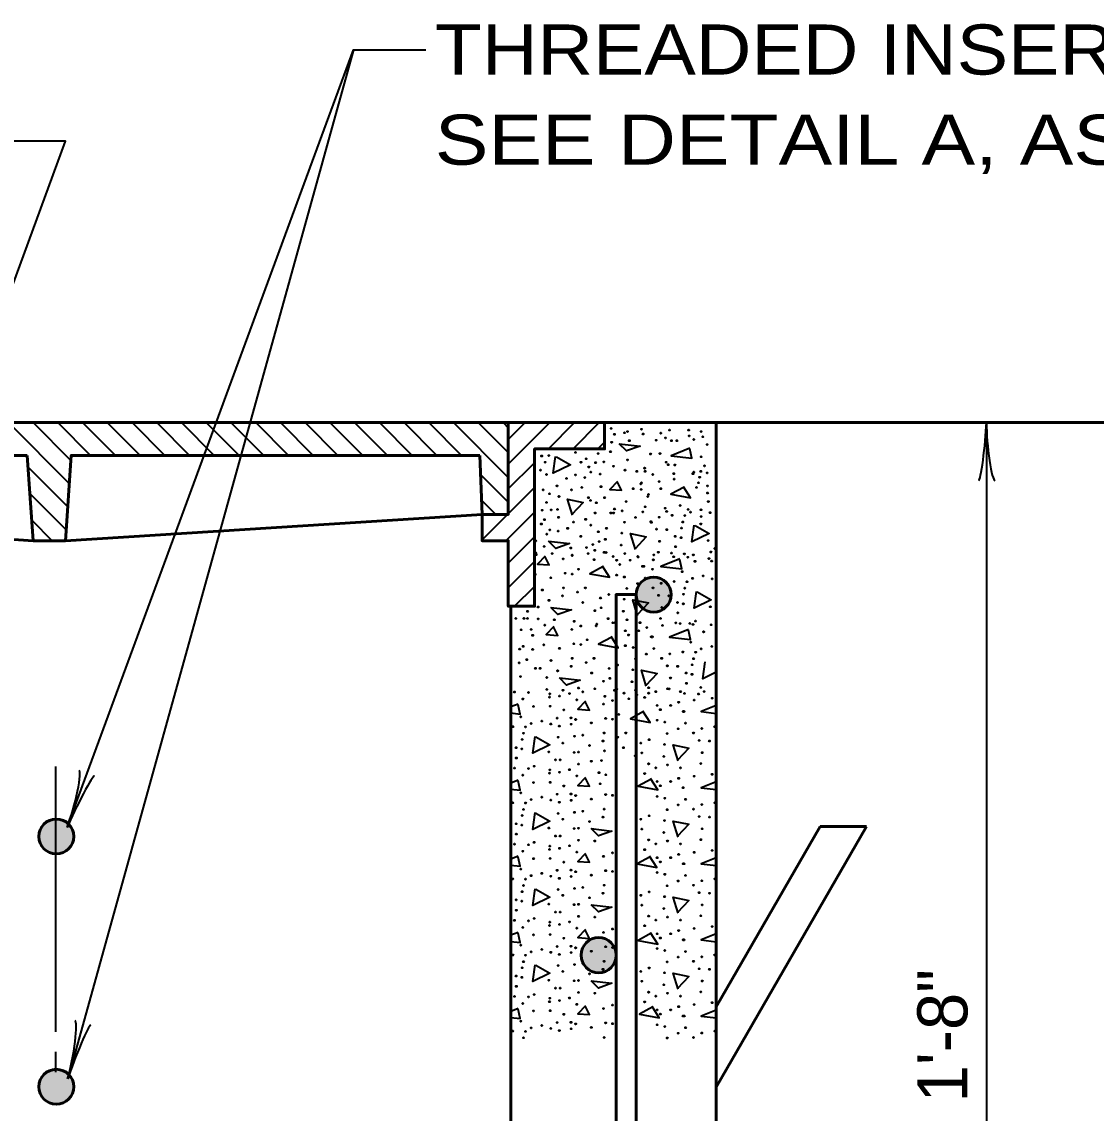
# Model space of a CAD drawing. Extents: x 788 to 1469, y -1 to 439.
# Drawn here: x 915.7 to 969.3, y 161.4 to 215.9 of the extents above; entities that cross this region are included whole.
import ezdxf

# ---------------------------------------------------------------- set-up
doc = ezdxf.new("R2010")
doc.units = 0
doc.layers.add('1', color=7, linetype='Continuous', lineweight=35)

msp = doc.modelspace()

# ---------------------------------------------------------------- hatches: boundary and pattern name
at = {"layer": '1'}
for points in [[(946.356, 187.287, 1), (948.101, 187.287, 1)], [(918.275, 175.212, 1), (916.531, 175.212, 1)], [(943.607, 169.287, 1), (945.361, 169.287, 1)], [(918.275, 162.716, 1), (916.531, 162.716, 1)]]:
    msp.add_hatch(color=256, dxfattribs=at).paths.add_polyline_path(points)

# ---------------------------------------------------------------- linework, layer by layer
for p, q in [((932.243, 214.486), (935.856, 214.486)), ((915.011, 195.872), (918.052, 192.831)), ((916.245, 195.872), (918.131, 193.986)), ((917.481, 195.872), (919.118, 194.235)), ((918.716, 195.872), (920.353, 194.235)), ((919.95, 195.872), (921.588, 194.235)), ((921.185, 195.872), (922.823, 194.235)), ((922.42, 195.872), (924.058, 194.235)), ((923.655, 195.872), (925.293, 194.235)), ((924.89, 195.872), (926.528, 194.235)), ((926.125, 195.872), (927.763, 194.235)), ((927.36, 195.872), (928.998, 194.235)), ((928.595, 195.872), (930.233, 194.235)), ((929.83, 195.872), (931.468, 194.235)), ((931.065, 195.872), (932.703, 194.235)), ((932.3, 195.872), (933.938, 194.235)), ((933.535, 195.872), (935.173, 194.235)), ((934.77, 195.872), (936.408, 194.235)), ((936.005, 195.872), (937.643, 194.235)), ((937.24, 195.872), (939.973, 193.14)), ((938.475, 195.872), (939.973, 194.375)), ((939.71, 195.872), (939.973, 195.609)), ((939.973, 195.033), (940.812, 195.872)), ((939.973, 193.798), (942.047, 195.872)), ((941.972, 194.562), (943.281, 195.872)), ((943.207, 194.562), (944.516, 195.872)), ((944.442, 194.562), (944.776, 194.897)), ((915.99, 193.657), (917.972, 191.675)), ((939.973, 192.564), (941.283, 193.873)), ((938.586, 193.291), (939.973, 191.904)), ((916.082, 192.331), (917.892, 190.52)), ((939.973, 191.328), (941.283, 192.638)), ((938.635, 192.007), (939.355, 191.287)), ((938.663, 190.019), (939.932, 191.287)), ((939.857, 189.978), (941.283, 191.403)), ((916.173, 191.004), (917.2, 189.978)), ((939.973, 188.859), (941.283, 190.168)), ((939.973, 187.624), (941.283, 188.933)), ((940.287, 186.703), (941.283, 187.698)), ((940.469, 181.824), (940.106, 181.677)), ((917.356, 178.703), (917.356, 165.453)), ((940.469, 178.024), (940.106, 177.877)), ((940.469, 174.224), (940.106, 174.077)), ((940.469, 170.424), (940.106, 170.277)), ((940.469, 166.624), (940.106, 166.477)), ((917.356, 164.453), (917.356, 163.453))]:
    msp.add_line(p, q, dxfattribs=at)
at = {"layer": '1', "lineweight": 53}
for p, q in [((894.126, 195.872), (939.973, 195.872)), ((939.973, 195.872), (950.356, 195.872)), ((939.973, 195.872), (939.973, 192.597)), ((950.356, 195.872), (950.356, 165.102)), ((950.356, 195.872), (999.683, 195.872)), ((915.95, 194.235), (895.549, 194.235)), ((938.55, 194.235), (938.663, 191.287)), ((895.436, 191.287), (916.244, 189.978)), ((917.855, 189.978), (938.663, 191.287)), ((940.106, 165.102), (940.106, 186.703)), ((950.356, 162.703), (957.856, 175.703)), ((950.356, 166.705), (955.547, 175.703)), ((957.856, 175.703), (955.547, 175.703)), ((940.106, 132.643), (940.106, 165.102)), ((950.356, 132.643), (950.356, 165.102))]:
    msp.add_line(p, q, dxfattribs=at)
at = {"layer": '1'}
for points in [[(917.95, 175.662), (932.243, 214.486), (917.979, 163.119)], [(911.684, 193.114), (917.856, 209.928), (913.665, 209.928)], [(963.856, 195.872), (963.856, 142.203), (963.856, 131.723), (963.856, 121.729), (963.856, 90.479)], [(949.04, 194.6), (948.1, 194.22), (949.14, 194.1), (949.04, 194.56)], [(942.373, 194.169), (943.073, 193.769), (942.213, 193.349), (942.333, 194.189)], [(945.42, 192.94), (945.04, 192.54), (945.62, 192.5), (945.42, 192.9)], [(948.751, 192.656), (948.091, 192.296), (949.072, 192.116), (948.712, 192.676)], [(943.173, 191.25), (942.933, 192.05), (943.712, 191.89), (943.152, 191.29)], [(949.3, 190.734), (950, 190.334), (949.14, 189.914), (949.26, 190.754)], [(946.32, 189.534), (946.08, 190.334), (946.861, 190.174), (946.3, 189.574)], [(941.809, 189.21), (941.429, 188.81), (942.009, 188.77), (941.809, 189.17)], [(948.529, 189.07), (947.589, 188.69), (948.629, 188.57), (948.529, 189.03)], [(944.709, 188.69), (944.049, 188.33), (945.029, 188.15), (944.669, 188.71)], [(949.409, 187.43), (950.109, 187.03), (949.249, 186.61), (949.369, 187.45)], [(946.429, 186.23), (946.189, 187.03), (946.969, 186.87), (946.409, 186.27)], [(942.242, 185.69), (941.862, 185.29), (942.442, 185.25), (942.242, 185.65)], [(948.962, 185.55), (948.022, 185.17), (949.062, 185.05), (948.962, 185.51)], [(945.142, 185.17), (944.482, 184.81), (945.462, 184.63), (945.102, 185.19)], [(950.356, 183.42), (949.682, 183.09), (949.802, 183.93)], [(946.862, 182.71), (946.622, 183.51), (947.402, 183.35), (946.842, 182.75)], [(940.106, 181.377), (940.569, 181.324), (940.469, 181.784)], [(943.829, 181.964), (943.449, 181.564), (944.029, 181.524), (943.829, 181.924)], [(946.729, 181.444), (946.069, 181.084), (947.049, 180.904), (946.689, 181.464)], [(950.356, 181.746), (949.609, 181.444), (950.356, 181.358)], [(941.349, 180.184), (942.049, 179.784), (941.189, 179.364), (941.309, 180.204)], [(948.449, 178.984), (948.209, 179.784), (948.989, 179.624), (948.429, 179.024)], [(940.106, 177.577), (940.569, 177.524), (940.469, 177.984)], [(943.829, 178.164), (943.449, 177.764), (944.029, 177.724), (943.829, 178.124)], [(947.114, 178.08), (946.454, 177.72), (947.434, 177.54), (947.074, 178.1)], [(950.356, 177.946), (949.609, 177.644), (950.356, 177.558)], [(941.349, 176.384), (942.049, 175.984), (941.189, 175.564), (941.309, 176.404)], [(948.449, 175.184), (948.209, 175.984), (948.989, 175.824), (948.429, 175.224)], [(943.829, 174.364), (943.449, 173.964), (944.029, 173.924), (943.829, 174.324)], [(940.106, 173.777), (940.569, 173.724), (940.469, 174.184)], [(947.062, 174.203), (946.402, 173.843), (947.382, 173.663), (947.022, 174.223)], [(950.356, 174.146), (949.609, 173.844), (950.356, 173.758)], [(941.349, 172.584), (942.049, 172.184), (941.189, 171.764), (941.309, 172.604)], [(948.449, 171.384), (948.209, 172.184), (948.989, 172.024), (948.429, 171.424)], [(943.829, 170.564), (943.449, 170.164), (944.029, 170.124), (943.829, 170.524)], [(940.106, 169.977), (940.569, 169.924), (940.469, 170.384)], [(947.114, 170.377), (946.454, 170.017), (947.434, 169.837), (947.074, 170.397)], [(950.356, 170.346), (949.609, 170.044), (950.356, 169.958)], [(941.349, 168.784), (942.049, 168.384), (941.189, 167.964), (941.309, 168.804)], [(948.449, 167.584), (948.209, 168.384), (948.989, 168.224), (948.429, 167.624)], [(943.829, 166.764), (943.449, 166.364), (944.029, 166.324), (943.829, 166.724)], [(947.191, 166.706), (946.531, 166.346), (947.511, 166.166), (947.151, 166.726)], [(940.106, 166.177), (940.569, 166.124), (940.469, 166.584)], [(950.356, 166.546), (949.609, 166.244), (950.356, 166.158)]]:
    msp.add_lwpolyline(points, dxfattribs=at)
at = {"layer": '1', "lineweight": 53}
for points in [[(944.776, 195.872), (944.776, 194.562), (941.283, 194.562), (941.283, 186.703), (939.973, 186.703), (939.973, 189.978), (938.663, 189.978), (938.663, 191.287), (939.973, 191.287), (939.973, 195.872)], [(938.55, 194.235), (918.149, 194.235), (917.855, 189.978), (916.244, 189.978), (915.95, 194.235)]]:
    msp.add_lwpolyline(points, dxfattribs=at)
at = {"layer": '1'}
for points in [[(945.513, 194.822), (946.553, 194.702), (945.873, 194.462)], [(941.981, 189.954), (943.02, 189.834), (942.341, 189.594)], [(942.089, 186.65), (943.129, 186.53), (942.449, 186.29)], [(942.522, 183.13), (943.562, 183.01), (942.882, 182.77)], [(944.109, 175.604), (945.149, 175.484), (944.469, 175.244)], [(944.109, 171.804), (945.149, 171.684), (944.469, 171.444)], [(944.109, 168.004), (945.149, 167.884), (944.469, 167.644)]]:
    msp.add_lwpolyline(points, close=True, dxfattribs=at)
at = {"layer": '1', "lineweight": 53}
msp.add_lwpolyline([(946.356, 126.703), (946.356, 187.287), (945.356, 187.287), (945.356, 127.703), (925.356, 127.703), (925.356, 126.703)], close=True, dxfattribs=at)
at = {"layer": '1'}
for centre in [(945.113, 195.582), (945.27, 195.287), (945.78, 195.366), (945.918, 195.425), (946.624, 195.543), (946.703, 195.307), (947.586, 195.346), (947.821, 195.111), (948.017, 195.503), (948.979, 195.503), (948.999, 195.209), (949.234, 195.032), (949.607, 195.425), (949.686, 195.17), (945.133, 194.895), (946.016, 194.973), (947.35, 194.993), (948.116, 194.973), (948.39, 194.973), (949.901, 194.777), (941.639, 194.208), (941.993, 194.227), (943.327, 194.384), (943.857, 194.07), (944.465, 194.326), (945.074, 194.424), (945.918, 194.011), (947.075, 194.306), (947.546, 194.326), (949.607, 194.169), (941.58, 193.501), (941.816, 193.894), (943.602, 193.894), (943.994, 193.658), (944.092, 193.403), (944.328, 193.874), (944.74, 193.913), (945.231, 193.697), (945.8, 193.501), (946.389, 193.442), (946.781, 193.599), (946.801, 193.442), (947.86, 193.894), (947.959, 193.776), (948.292, 193.756), (949.234, 193.403), (949.587, 193.442), (949.764, 193.717), (941.875, 193.285), (942.876, 193.089), (943.327, 193.265), (943.798, 193.128), (944.563, 193.305), (946.624, 192.873), (947.193, 193.285), (947.507, 192.932), (948.233, 193.324), (948.253, 193.05), (949.195, 193.324), (949.47, 192.873), (949.529, 193.148), (949.901, 193.364), (941.718, 192.519), (942.032, 192.323), (942.405, 192.716), (943.131, 192.519), (943.641, 192.637), (944.603, 192.677), (946.212, 192.578), (946.585, 192.814), (946.604, 192.539), (947.586, 192.578), (949.372, 192.637), (949.921, 192.716), (949.921, 192.362), (941.875, 191.891), (942.503, 192.186), (943.975, 192.127), (944.073, 191.989), (944.367, 191.872), (944.779, 192.127), (945.859, 191.931), (946.938, 192.186), (946.977, 192.284), (949.96, 191.931), (941.659, 191.499), (942.11, 191.518), (942.424, 191.538), (944.308, 191.361), (945.093, 191.361), (945.231, 191.361), (945.275, 191.563), (945.659, 191.471), (946.693, 191.418), (946.801, 191.675), (947.802, 191.597), (947.88, 191.44), (948.151, 191.245), (948.549, 191.736), (948.787, 191.232), (948.959, 191.538), (949.065, 191.404), (949.596, 191.524), (950.046, 191.378), (941.62, 190.812), (941.777, 191.028), (942.483, 191.145), (943.229, 190.91), (943.837, 191.047), (944.092, 190.753), (945.779, 190.901), (946.322, 191.139), (947.091, 190.927), (947.115, 190.89), (947.502, 191.152), (948.681, 190.914), (949.587, 190.812), (949.607, 191.185), (941.896, 190.304), (942.051, 190.517), (942.464, 190.458), (942.935, 190.596), (943.592, 190.198), (944.467, 190.423), (944.877, 190.596), (945.646, 190.357), (947.369, 190.556), (947.886, 190.529), (948.31, 190.198), (948.602, 190.132), (948.615, 190.609), (941.352, 189.973), (941.757, 189.693), (943.092, 189.614), (943.877, 189.634), (944.188, 189.787), (944.506, 189.933), (944.819, 190.046), (945.606, 189.76), (947.528, 189.946), (948.323, 189.681), (949.953, 189.986), (950.285, 189.588), (941.352, 189.376), (941.368, 189.281), (942.161, 189.336), (942.706, 189.069), (943.155, 189.257), (943.157, 189.241), (943.965, 189.334), (944.289, 189.496), (944.76, 189.4), (944.851, 189.389), (945.209, 189.19), (945.792, 189.336), (946.441, 189.19), (946.457, 189.162), (947.239, 189.268), (947.462, 189.402), (948.127, 189.36), (948.231, 189.177), (948.763, 189.321), (948.933, 189.151), (949.211, 189.27), (949.993, 189.084), (950.088, 189.413), (943.475, 188.552), (944.255, 189.031), (945.383, 189.002), (945.542, 188.79), (946.059, 189.002), (946.682, 188.698), (946.735, 188.698), (947.174, 188.554), (947.213, 189.025), (949.293, 188.949), (950.128, 188.963), (941.315, 188.3), (942.097, 188.127), (942.812, 188.353), (943.157, 188.313), (945.383, 188.26), (945.768, 188.167), (946.801, 188.114), (948.657, 188.432), (949.174, 188.101), (949.704, 188.22), (950.155, 188.074), (941.672, 187.518), (942.733, 187.624), (943.422, 187.412), (943.819, 187.624), (945.887, 187.597), (946.43, 187.836), (947.199, 187.624), (947.61, 187.849), (948.259, 187.942), (948.789, 187.61), (948.895, 187.929), (942.004, 187.001), (942.68, 187.226), (943.7, 186.894), (944.575, 187.12), (944.986, 187.292), (945.754, 187.054), (947.477, 187.252), (947.994, 187.226), (948.418, 186.894), (948.723, 187.305), (940.933, 186.453), (941.46, 186.669), (944.297, 186.484), (944.615, 186.629), (945.715, 186.457), (947.636, 186.643), (948.432, 186.377), (948.71, 186.828), (950.062, 186.682), (940.344, 186.1), (940.756, 186.1), (940.933, 186.1), (941.46, 186.073), (942.269, 186.033), (943.263, 185.953), (944.398, 185.814), (944.959, 186.086), (945.194, 185.88), (945.317, 185.887), (945.9, 186.033), (946.55, 185.887), (947.57, 186.099), (948.339, 185.874), (948.56, 185.84), (949.041, 185.847), (949.196, 185.801), (949.32, 185.966), (950.102, 185.781), (940.619, 185.531), (941.109, 185.55), (941.188, 185.256), (941.801, 185.761), (943.139, 185.549), (943.59, 185.721), (944.363, 185.728), (945.816, 185.482), (945.976, 185.27), (946.492, 185.482), (946.89, 185.642), (947.672, 185.748), (949.726, 185.429), (940.717, 184.706), (941.748, 184.78), (943.245, 184.833), (943.59, 184.793), (943.908, 185.032), (945.817, 184.74), (947.115, 185.178), (947.168, 185.178), (949.09, 184.912), (950.137, 184.7), (940.54, 184.569), (941.188, 184.549), (942.53, 184.607), (946.201, 184.647), (946.864, 184.316), (947.235, 184.594), (948.043, 184.329), (948.692, 184.422), (949.329, 184.409), (949.607, 184.581), (940.521, 183.882), (940.894, 184.039), (941.325, 183.607), (941.561, 183.607), (942.106, 183.998), (943.113, 183.706), (943.166, 184.104), (943.855, 183.892), (944.253, 184.104), (945.008, 183.6), (945.419, 183.772), (946.32, 184.077), (947.632, 184.104), (947.911, 183.732), (948.427, 183.706), (949.156, 183.785), (949.223, 184.09), (940.58, 183.195), (941.894, 183.149), (942.437, 183.481), (944.133, 183.374), (945.048, 183.109), (946.188, 183.534), (948.07, 183.123), (948.851, 183.374), (949.143, 183.308), (941.894, 182.553), (942.702, 182.513), (943.481, 182.626), (944.289, 182.586), (944.73, 182.964), (945.283, 182.507), (945.392, 182.566), (946.148, 182.937), (946.333, 182.513), (946.98, 182.639), (947.92, 182.586), (948.003, 182.579), (948.865, 182.857), (949.59, 182.653), (940.279, 182.427), (940.703, 182.074), (940.982, 182.401), (942.028, 182.167), (942.042, 182.334), (942.532, 182.22), (943.022, 182.348), (943.388, 182.034), (943.696, 182.433), (944.796, 182.208), (945.177, 181.995), (945.75, 182.367), (945.986, 182.087), (946.383, 182.281), (946.781, 182.154), (946.983, 182.367), (947.337, 182.44), (948.57, 182.44), (948.772, 182.354), (949.259, 182.021), (949.474, 182.327), (949.753, 182.446), (950.147, 182.114), (941.233, 181.703), (942.068, 181.716), (942.744, 181.531), (944.726, 181.822), (947.404, 181.756), (947.563, 181.544), (948.08, 181.756), (948.477, 181.915), (948.702, 181.451), (948.755, 181.451), (940.597, 181.186), (941.644, 180.974), (942.413, 181.12), (943.102, 181.133), (943.335, 181.053), (944.117, 180.881), (944.832, 181.106), (945.177, 181.067), (945.495, 181.305), (947.404, 181.014), (947.788, 180.921), (948.822, 180.868), (940.2, 180.695), (940.73, 180.364), (940.836, 180.682), (941.114, 180.854), (942.095, 180.828), (942.519, 180.722), (943.115, 180.815), (944.753, 180.377), (945.84, 180.377), (947.907, 180.351), (948.451, 180.589), (949.219, 180.377), (949.63, 180.603), (950.28, 180.695), (940.663, 180.059), (942.466, 180.165), (942.691, 179.873), (943.274, 180.218), (943.693, 180.271), (944.7, 179.979), (945.442, 180.165), (946.595, 179.873), (947.006, 180.046), (947.775, 179.807), (949.498, 180.006), (950.014, 179.979), (940.359, 179.648), (940.65, 179.582), (942.002, 179.436), (943.255, 179.407), (943.481, 179.423), (944.024, 179.754), (944.777, 179.488), (945.72, 179.648), (946.317, 179.237), (946.635, 179.383), (949.657, 179.396), (940.372, 179.131), (941.26, 178.72), (942.333, 179.038), (942.559, 179.038), (943.481, 178.826), (944.117, 178.966), (944.626, 179.001), (946.98, 178.839), (947.735, 179.211), (947.92, 178.786), (949.59, 178.853), (940.279, 178.627), (940.703, 178.274), (940.982, 178.601), (942.028, 178.367), (942.042, 178.534), (942.532, 178.42), (943.022, 178.548), (943.388, 178.234), (944.499, 178.399), (944.846, 178.295), (946.781, 178.354), (947.337, 178.64), (948.57, 178.64), (949.259, 178.221), (950.147, 178.314), (941.233, 177.903), (942.068, 177.916), (942.744, 177.731), (944.557, 177.843), (947.404, 177.956), (947.563, 177.744), (948.08, 177.956), (948.477, 178.115), (948.702, 177.651), (940.597, 177.386), (941.114, 177.054), (941.644, 177.174), (942.413, 177.32), (943.102, 177.333), (943.335, 177.253), (944.117, 177.081), (944.832, 177.306), (945.177, 177.267), (947.404, 177.214), (947.788, 177.121), (948.822, 177.068), (940.2, 176.895), (940.73, 176.564), (940.836, 176.882), (942.095, 177.028), (942.519, 176.922), (943.115, 177.015), (944.753, 176.577), (947.907, 176.551), (948.451, 176.789), (949.219, 176.577), (949.63, 176.803), (950.28, 176.895), (940.663, 176.259), (942.466, 176.365), (942.691, 176.073), (943.274, 176.418), (943.693, 176.471), (944.7, 176.179), (946.595, 176.073), (947.006, 176.246), (947.775, 176.007), (949.498, 176.206), (950.014, 176.179), (940.359, 175.848), (940.65, 175.782), (942.002, 175.636), (943.255, 175.607), (943.481, 175.623), (944.024, 175.954), (946.635, 175.583), (949.657, 175.596), (940.372, 175.331), (941.26, 174.92), (942.333, 175.238), (942.559, 175.238), (943.481, 175.026), (944.289, 174.986), (946.98, 175.039), (947.735, 175.411), (947.92, 174.986), (949.59, 175.053), (940.279, 174.827), (940.703, 174.474), (940.982, 174.801), (942.028, 174.567), (942.042, 174.734), (942.532, 174.62), (943.022, 174.748), (943.388, 174.434), (945.177, 174.395), (946.781, 174.554), (947.337, 174.84), (948.57, 174.84), (949.259, 174.421), (950.147, 174.514), (941.233, 174.103), (942.068, 174.116), (942.744, 173.931), (944.726, 174.222), (947.404, 174.156), (947.563, 173.944), (948.08, 174.156), (948.477, 174.315), (948.702, 173.851), (948.755, 173.851), (940.597, 173.586), (941.114, 173.254), (941.644, 173.374), (942.413, 173.52), (943.102, 173.533), (943.335, 173.453), (944.117, 173.281), (944.832, 173.506), (945.177, 173.467), (947.404, 173.414), (947.788, 173.321), (948.822, 173.268), (940.2, 173.095), (940.73, 172.764), (940.836, 173.082), (942.095, 173.228), (942.519, 173.122), (943.115, 173.215), (944.753, 172.777), (947.907, 172.751), (948.451, 172.989), (949.219, 172.777), (949.63, 173.003), (950.28, 173.095), (940.663, 172.459), (942.466, 172.565), (942.691, 172.273), (943.274, 172.618), (943.693, 172.671), (944.024, 172.154), (944.7, 172.379), (946.595, 172.273), (947.006, 172.446), (947.775, 172.207), (949.498, 172.406), (950.014, 172.379), (940.359, 172.048), (940.65, 171.982), (942.002, 171.836), (943.255, 171.807), (943.481, 171.823), (946.635, 171.783), (947.735, 171.611), (949.657, 171.796), (940.372, 171.531), (941.26, 171.12), (942.333, 171.438), (942.559, 171.438), (943.481, 171.226), (944.289, 171.186), (946.98, 171.239), (947.92, 171.186), (949.59, 171.253), (940.279, 171.027), (940.703, 170.674), (940.982, 171.001), (942.028, 170.767), (942.042, 170.934), (942.532, 170.82), (943.022, 170.948), (943.388, 170.634), (945.177, 170.595), (946.781, 170.754), (947.337, 171.04), (948.477, 170.515), (948.57, 171.04), (949.259, 170.621), (950.147, 170.714), (941.233, 170.303), (942.068, 170.316), (942.744, 170.131), (944.726, 170.422), (947.404, 170.356), (947.563, 170.144), (948.08, 170.356), (948.702, 170.051), (948.755, 170.051), (940.597, 169.786), (941.114, 169.454), (941.644, 169.574), (942.095, 169.428), (942.413, 169.72), (943.102, 169.733), (943.335, 169.653), (944.117, 169.481), (944.832, 169.706), (945.177, 169.667), (947.404, 169.614), (947.788, 169.521), (948.822, 169.468), (940.2, 169.295), (940.73, 168.964), (940.836, 169.282), (942.519, 169.322), (943.115, 169.415), (944.753, 168.977), (947.907, 168.951), (948.451, 169.189), (949.219, 168.977), (949.63, 169.203), (950.28, 169.295), (940.663, 168.659), (942.466, 168.765), (942.691, 168.473), (943.274, 168.818), (943.693, 168.871), (944.024, 168.354), (944.7, 168.579), (946.595, 168.473), (947.006, 168.646), (947.775, 168.407), (949.498, 168.606), (950.014, 168.579), (940.359, 168.248), (940.65, 168.182), (942.002, 168.036), (943.255, 168.007), (943.481, 168.023), (946.635, 167.983), (947.735, 167.811), (949.657, 167.996), (940.372, 167.731), (941.26, 167.32), (942.333, 167.638), (942.559, 167.638), (943.481, 167.426), (944.289, 167.386), (946.98, 167.439), (947.92, 167.386), (949.59, 167.453), (940.279, 167.227), (940.703, 166.874), (940.982, 167.201), (942.028, 166.967), (942.042, 167.134), (942.532, 167.02), (943.022, 167.148), (943.388, 166.834), (945.177, 166.795), (946.781, 166.954), (947.337, 167.24), (948.477, 166.715), (948.57, 167.24), (949.259, 166.821), (950.147, 166.914), (941.233, 166.503), (942.068, 166.516), (942.744, 166.331), (944.726, 166.622), (947.404, 166.556), (947.563, 166.344), (948.08, 166.556), (948.702, 166.251), (948.755, 166.251), (940.597, 165.986), (941.114, 165.654), (941.644, 165.774), (942.095, 165.628), (942.413, 165.92), (943.102, 165.933), (943.115, 165.615), (943.335, 165.853), (944.117, 165.681), (944.832, 165.906), (945.177, 165.867), (947.404, 165.814), (947.788, 165.721), (948.822, 165.668), (940.2, 165.495), (940.73, 165.164), (940.836, 165.482), (942.519, 165.522), (944.753, 165.177), (947.907, 165.151), (948.451, 165.389), (949.219, 165.177), (949.63, 165.403), (950.28, 165.495)]:
    msp.add_circle(centre, 0.0265, dxfattribs=at)
at = {"layer": '1', "lineweight": 53}
for centre, radius in [((947.228, 187.287), 0.872), ((917.403, 175.212), 0.872), ((944.484, 169.287), 0.877), ((917.403, 162.716), 0.872)]:
    msp.add_circle(centre, radius, dxfattribs=at)
at = {"layer": '1'}
for centre in [(950.359, 178.627), (950.359, 174.827), (950.359, 171.027), (950.359, 167.227)]:
    msp.add_arc(centre, 0.0265, 96.1831, 263.8169, dxfattribs=at)
at = {"layer": '1', "lineweight": 40}
for centre, major_axis, ratio, start_param, end_param in [((963.637, 194.743), (0.176, 1.756), 0.07063, 3.140715, 5.41811), ((964.124, 194.772), (-0.156, 1.786), 0.122415, 0.896353, 3.141593), ((918.068, 176.782), (-0.47, -1.73), 0.122415, 0.896353, 3.141593), ((918.536, 176.641), (-0.772, -1.588), 0.07063, 3.140715, 5.41811), ((918.005, 164.245), (-0.327, -1.762), 0.122415, 0.896353, 3.141593), ((918.483, 164.142), (-0.639, -1.645), 0.07063, 3.140715, 5.41811)]:
    msp.add_ellipse(centre, major_axis=major_axis, ratio=ratio, start_param=start_param, end_param=end_param, dxfattribs=at)

# ---------------------------------------------------------------- texts
at = {"layer": '1'}
for s, width, p in [('THREADED INSERT (TYP.)', 1.15, (936.304, 213.25)), ("SEE DETAIL A, AS REQ'D. 2 SETS MIN.", 1.2, (936.304, 208.75))]:
    msp.add_text(s, height=2.5, dxfattribs=dict(at, width=width)).set_placement(p)
msp.add_text('1\'-8"', height=2.5, rotation=90, dxfattribs=at).set_placement((962.895, 161.939))

doc.saveas('drawing.dxf')
